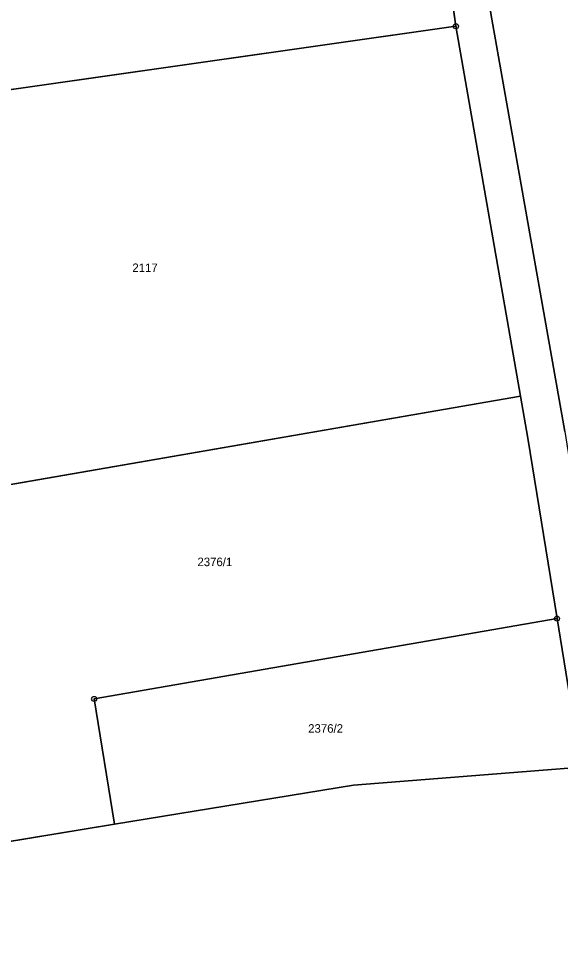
# Model space of a CAD drawing. Extents: x -689422 to -685210, y -987725 to -982160.
# Drawn here: x -687242.2 to -687134.4, y -986703.2 to -986516.1 of the extents above; entities that cross this region are included whole.
import ezdxf

# ---------------------------------------------------------------- set-up
doc = ezdxf.new("R2010")
doc.units = 0
for name, color, linetype in [('KN_Hranice_parcel', 7, 'Continuous'), ('KN_Parcelni cisla', 7, 'Continuous'), ('KN_Polygon parcely', 7, 'Continuous'), ('KN_POZEMKY_ORNA PUDA', 7, 'Continuous'), ('KN_POZEMKY_OSTATNI PLOCHA', 7, 'Continuous'), ('KN_POZEMKY_TTP', 7, 'Continuous'), ('KN_VYUZITI_17_ostatni plocha_ostatni komunikace', 7, 'Continuous'), ('KN_Značky bodu BP', 7, 'Continuous')]:
    doc.layers.add(name, color=color, linetype=linetype)

msp = doc.modelspace()

# ---------------------------------------------------------------- linework, layer by layer
at = {"layer": 'KN_Hranice_parcel'}
for p, q in [((-687280.63, -986535.42), (-687155.17, -986517.61)), ((-687142.33, -986591.25), (-687155.17, -986517.61)), ((-687265.43, -986612.6), (-687142.33, -986591.25)), ((-687140.87, -986599.63), (-687142.33, -986591.25)), ((-687135.04, -986635.57), (-687140.87, -986599.63)), ((-687227.24, -986651.58), (-687135.04, -986635.57)), ((-687223.16, -986676.53), (-687227.24, -986651.58)), ((-687132.73, -986665.38), (-687175.57, -986668.76)), ((-687175.57, -986668.76), (-687223.16, -986676.53)), ((-687223.16, -986676.53), (-687251.84, -986681.22))]:
    msp.add_line(p, q, dxfattribs=at)
for points in [[(-687155.17, -986517.61), (-687171.08, -986406.01), (-687173.3, -986379)], [(-687158.04, -986449.96), (-687148.24, -986515.1), (-687133.5, -986598.3)], [(-687132.73, -986665.38), (-687130.24, -986665.18), (-687135.04, -986635.57)]]:
    msp.add_lwpolyline(points, dxfattribs=at)
at = {"layer": 'KN_Polygon parcely'}
for points in [[(-687133.5, -986598.3), (-687148.24, -986515.1), (-687158.04, -986449.96), (-687159.12, -986441.98), (-687161.78, -986418.73), (-687164.03, -986405.2), (-687162.93, -986395.38), (-687174.58, -986328.8), (-687177.47, -986314.67), (-687180.02, -986304.74), (-687200.12, -986226.55)], [(-687205.96, -986239.19), (-687187.85, -986306.63), (-687173.3, -986379), (-687171.08, -986406.01), (-687155.17, -986517.61), (-687142.33, -986591.25), (-687140.87, -986599.63), (-687135.04, -986635.57), (-687130.24, -986665.18)]]:
    msp.add_lwpolyline(points, dxfattribs=at)
for points in [[(-687148.24, -986515.1), (-687133.5, -986598.3), (-687119.3, -986688), (-687070.16, -986677.59), (-687072.96, -986662.37), (-687079.74, -986616.2), (-687085.25, -986493.64), (-687093.11, -986413.86), (-687115.82, -986288.44), (-687117.58, -986291.9), (-687168.76, -986319.83), (-687173.06, -986323.05), (-687174.58, -986328.8), (-687162.93, -986395.38), (-687164.03, -986405.2), (-687161.78, -986418.73), (-687160.66, -986421.22), (-687157.3, -986442.09), (-687158.04, -986449.96)], [(-687171.08, -986406.01), (-687173.3, -986379), (-687307.1, -986402.43), (-687280.63, -986535.42), (-687155.17, -986517.61)], [(-687142.33, -986591.25), (-687155.17, -986517.61), (-687280.63, -986535.42), (-687265.43, -986612.6)], [(-687140.87, -986599.63), (-687142.33, -986591.25), (-687265.43, -986612.6), (-687251.84, -986681.22), (-687223.16, -986676.53), (-687227.24, -986651.58), (-687135.04, -986635.57)], [(-687130.24, -986665.18), (-687135.04, -986635.57), (-687227.24, -986651.58), (-687223.16, -986676.53), (-687175.57, -986668.76), (-687132.73, -986665.38)], [(-687132.73, -986665.38), (-687175.57, -986668.76), (-687223.16, -986676.53), (-687251.84, -986681.22), (-687260.77, -986682.68), (-687249.1, -986736.08), (-687233, -986786.07), (-687222.58, -986825.34), (-687193.41, -986820.33), (-687156.89, -986815.37), (-687149.53, -986814.63), (-687114.53, -986811.14), (-687123.74, -986736.78)]]:
    msp.add_lwpolyline(points, close=True, dxfattribs=at)
at = {"layer": 'KN_POZEMKY_ORNA PUDA'}
for p, q in [((-687171.08, -986406.01), (-687155.17, -986517.61)), ((-687133.5, -986598.3), (-687148.24, -986515.1)), ((-687155.17, -986517.61), (-687280.63, -986535.42)), ((-687280.63, -986535.42), (-687155.17, -986517.61)), ((-687155.17, -986517.61), (-687142.33, -986591.25)), ((-687142.33, -986591.25), (-687265.43, -986612.6)), ((-687265.43, -986612.6), (-687142.33, -986591.25)), ((-687142.33, -986591.25), (-687140.87, -986599.63)), ((-687140.87, -986599.63), (-687135.04, -986635.57)), ((-687135.04, -986635.57), (-687227.24, -986651.58)), ((-687227.24, -986651.58), (-687135.04, -986635.57)), ((-687135.04, -986635.57), (-687130.24, -986665.18)), ((-687227.24, -986651.58), (-687223.16, -986676.53)), ((-687223.16, -986676.53), (-687227.24, -986651.58)), ((-687132.73, -986665.38), (-687175.57, -986668.76)), ((-687175.57, -986668.76), (-687223.16, -986676.53)), ((-687223.16, -986676.53), (-687251.84, -986681.22))]:
    msp.add_line(p, q, dxfattribs=at)
at = {"layer": 'KN_POZEMKY_OSTATNI PLOCHA'}
for p, q in [((-687155.17, -986517.61), (-687171.08, -986406.01)), ((-687148.24, -986515.1), (-687133.5, -986598.3)), ((-687142.33, -986591.25), (-687155.17, -986517.61)), ((-687140.87, -986599.63), (-687142.33, -986591.25)), ((-687135.04, -986635.57), (-687140.87, -986599.63)), ((-687130.24, -986665.18), (-687135.04, -986635.57))]:
    msp.add_line(p, q, dxfattribs=at)
at = {"layer": 'KN_POZEMKY_TTP'}
for p, q in [((-687175.57, -986668.76), (-687132.73, -986665.38)), ((-687223.16, -986676.53), (-687175.57, -986668.76)), ((-687251.84, -986681.22), (-687223.16, -986676.53))]:
    msp.add_line(p, q, dxfattribs=at)
at = {"layer": 'KN_VYUZITI_17_ostatni plocha_ostatni komunikace'}
for p, q in [((-687155.17, -986517.61), (-687171.08, -986406.01)), ((-687148.24, -986515.1), (-687133.5, -986598.3)), ((-687142.33, -986591.25), (-687155.17, -986517.61)), ((-687140.87, -986599.63), (-687142.33, -986591.25)), ((-687135.04, -986635.57), (-687140.87, -986599.63)), ((-687130.24, -986665.18), (-687135.04, -986635.57))]:
    msp.add_line(p, q, dxfattribs=at)
at = {"layer": 'KN_Značky bodu BP'}
for centre, radius in [((-687155.17, -986517.61), 0.5), ((-687155.17, -986517.61), 0.0303), ((-687135.04, -986635.57), 0.5), ((-687135.04, -986635.57), 0.0303), ((-687227.24, -986651.58), 0.5), ((-687227.24, -986651.58), 0.0303)]:
    msp.add_circle(centre, radius, dxfattribs=at)

# ---------------------------------------------------------------- texts
at = {"layer": 'KN_Parcelni cisla'}
for s, p in [('2117', (-687219.63, -986566.56)), ('2376/1', (-687206.67, -986625.13)), ('2376/2', (-687184.61, -986658.3))]:
    msp.add_text(s, height=1.7, dxfattribs=at).set_placement(p)

doc.saveas('drawing.dxf')
